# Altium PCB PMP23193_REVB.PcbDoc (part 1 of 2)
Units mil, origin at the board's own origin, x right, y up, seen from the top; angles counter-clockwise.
Board outline 5000 x 3500 mil, 4 copper layers (Component Side, Signal Layer 1, Signal Layer 2, Solder Side), stack 33.234 mil thick; 89 components, 40 nets, 217 pads, 130 vias.
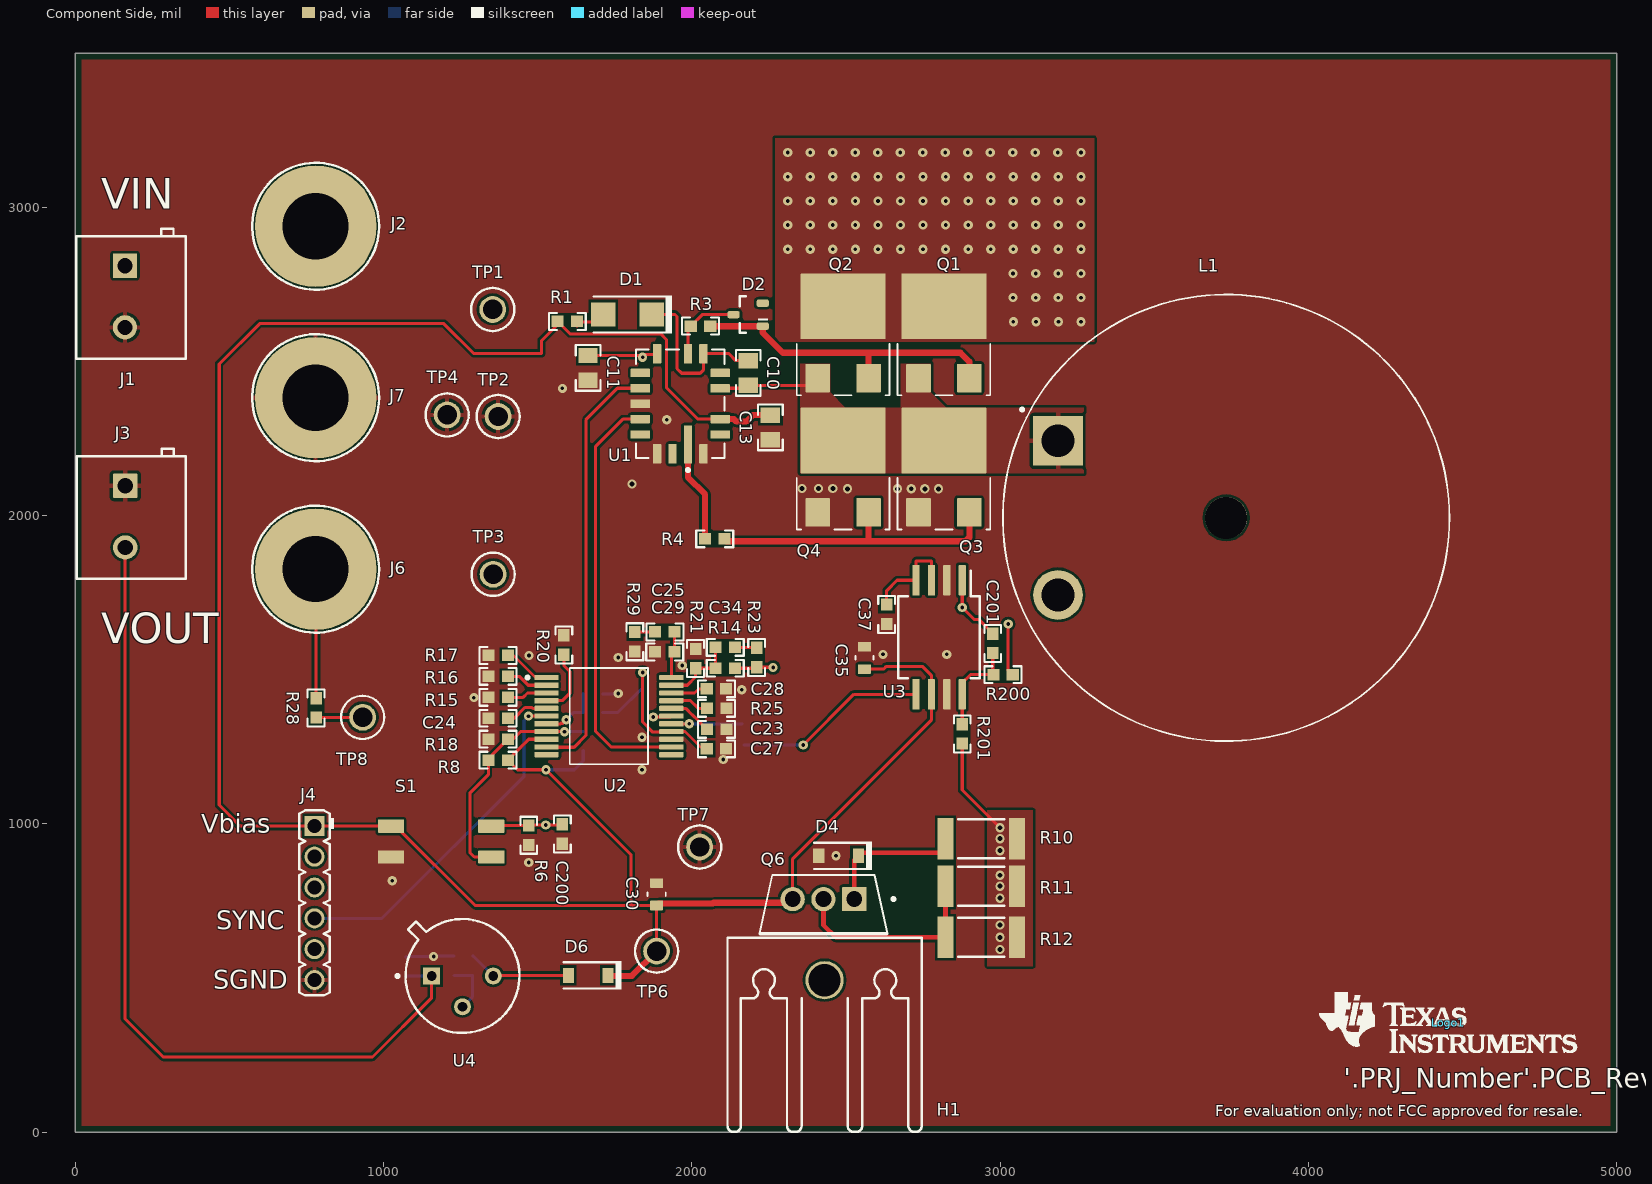
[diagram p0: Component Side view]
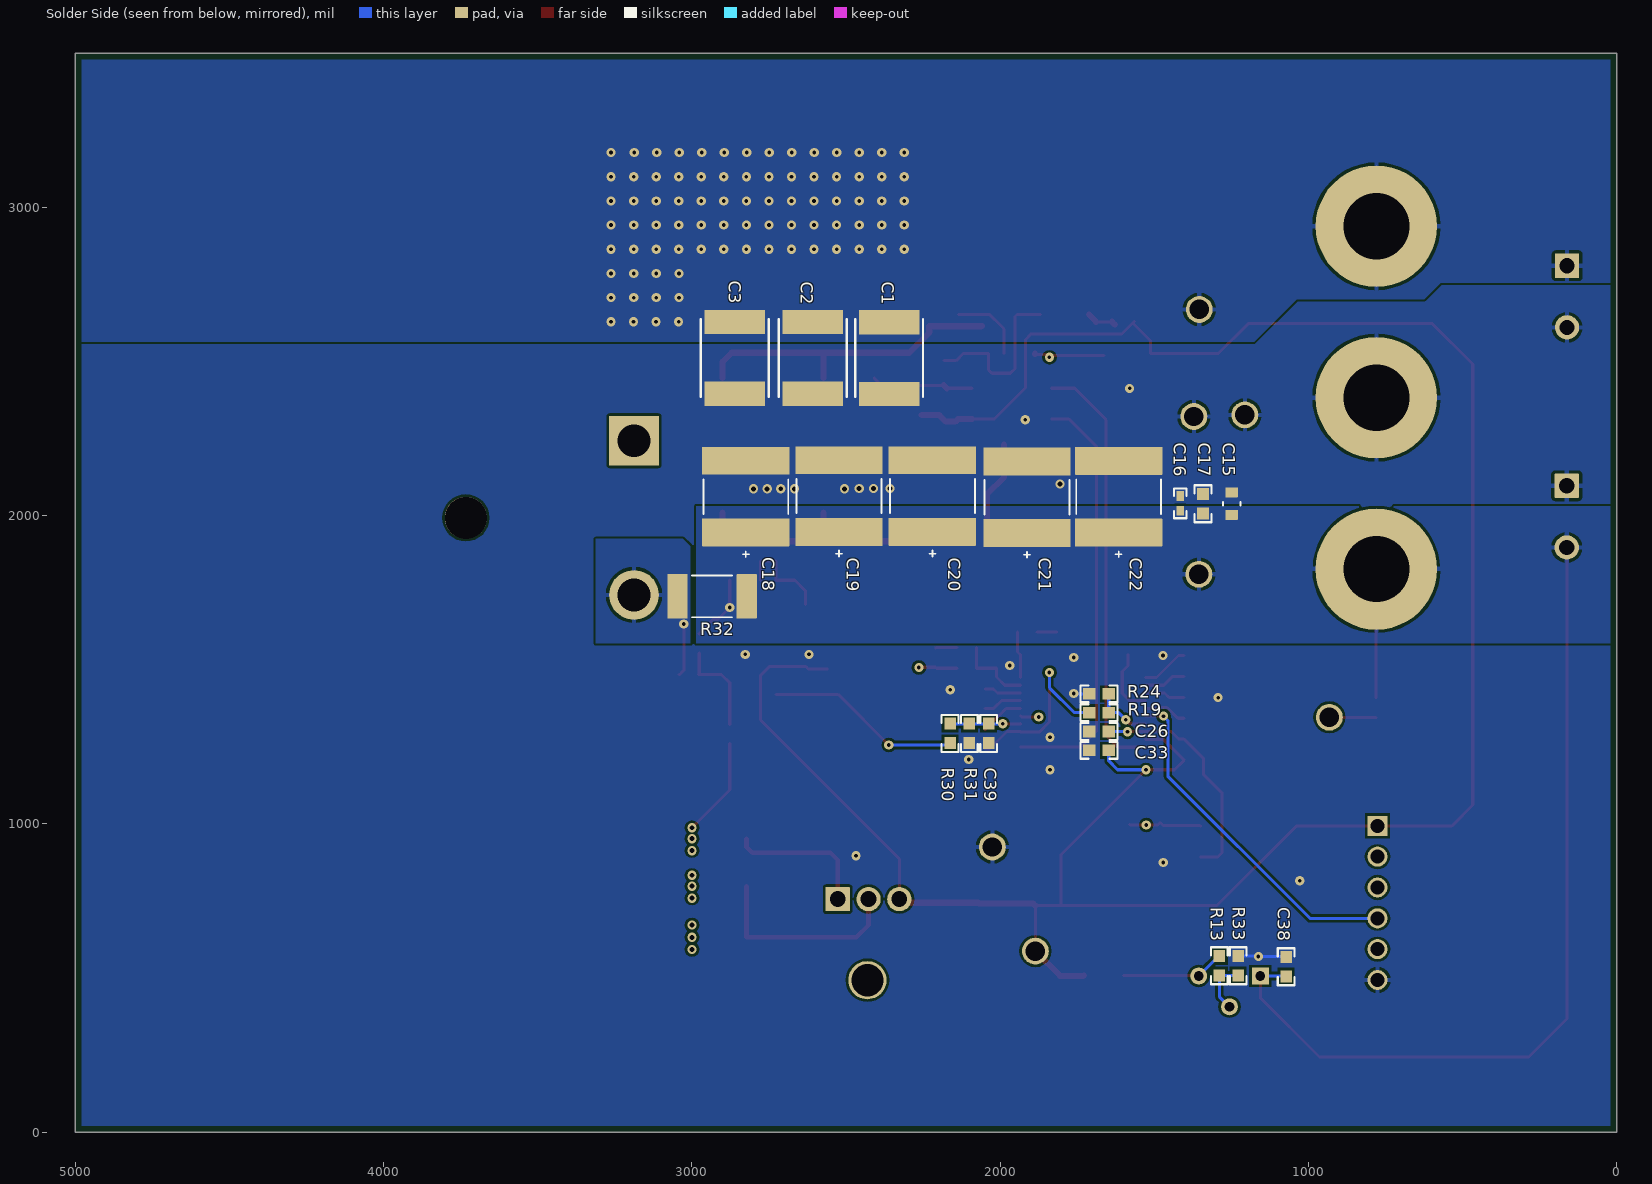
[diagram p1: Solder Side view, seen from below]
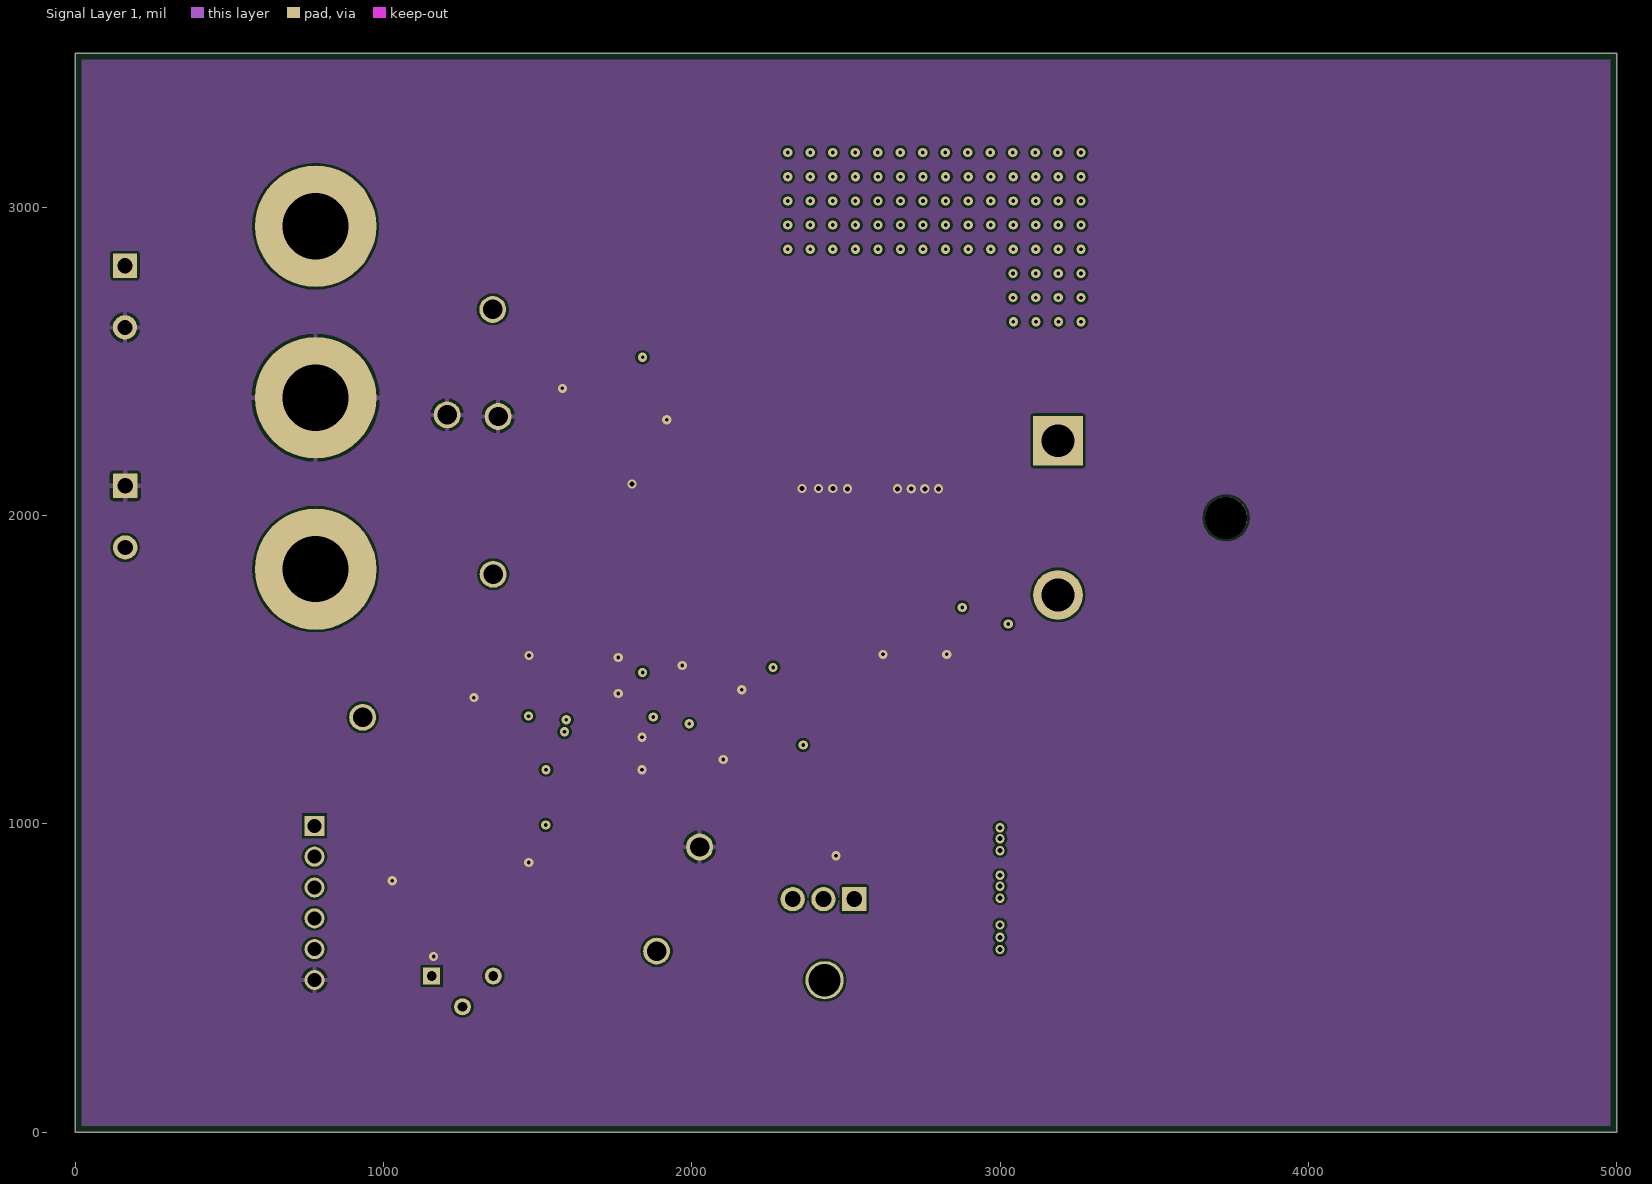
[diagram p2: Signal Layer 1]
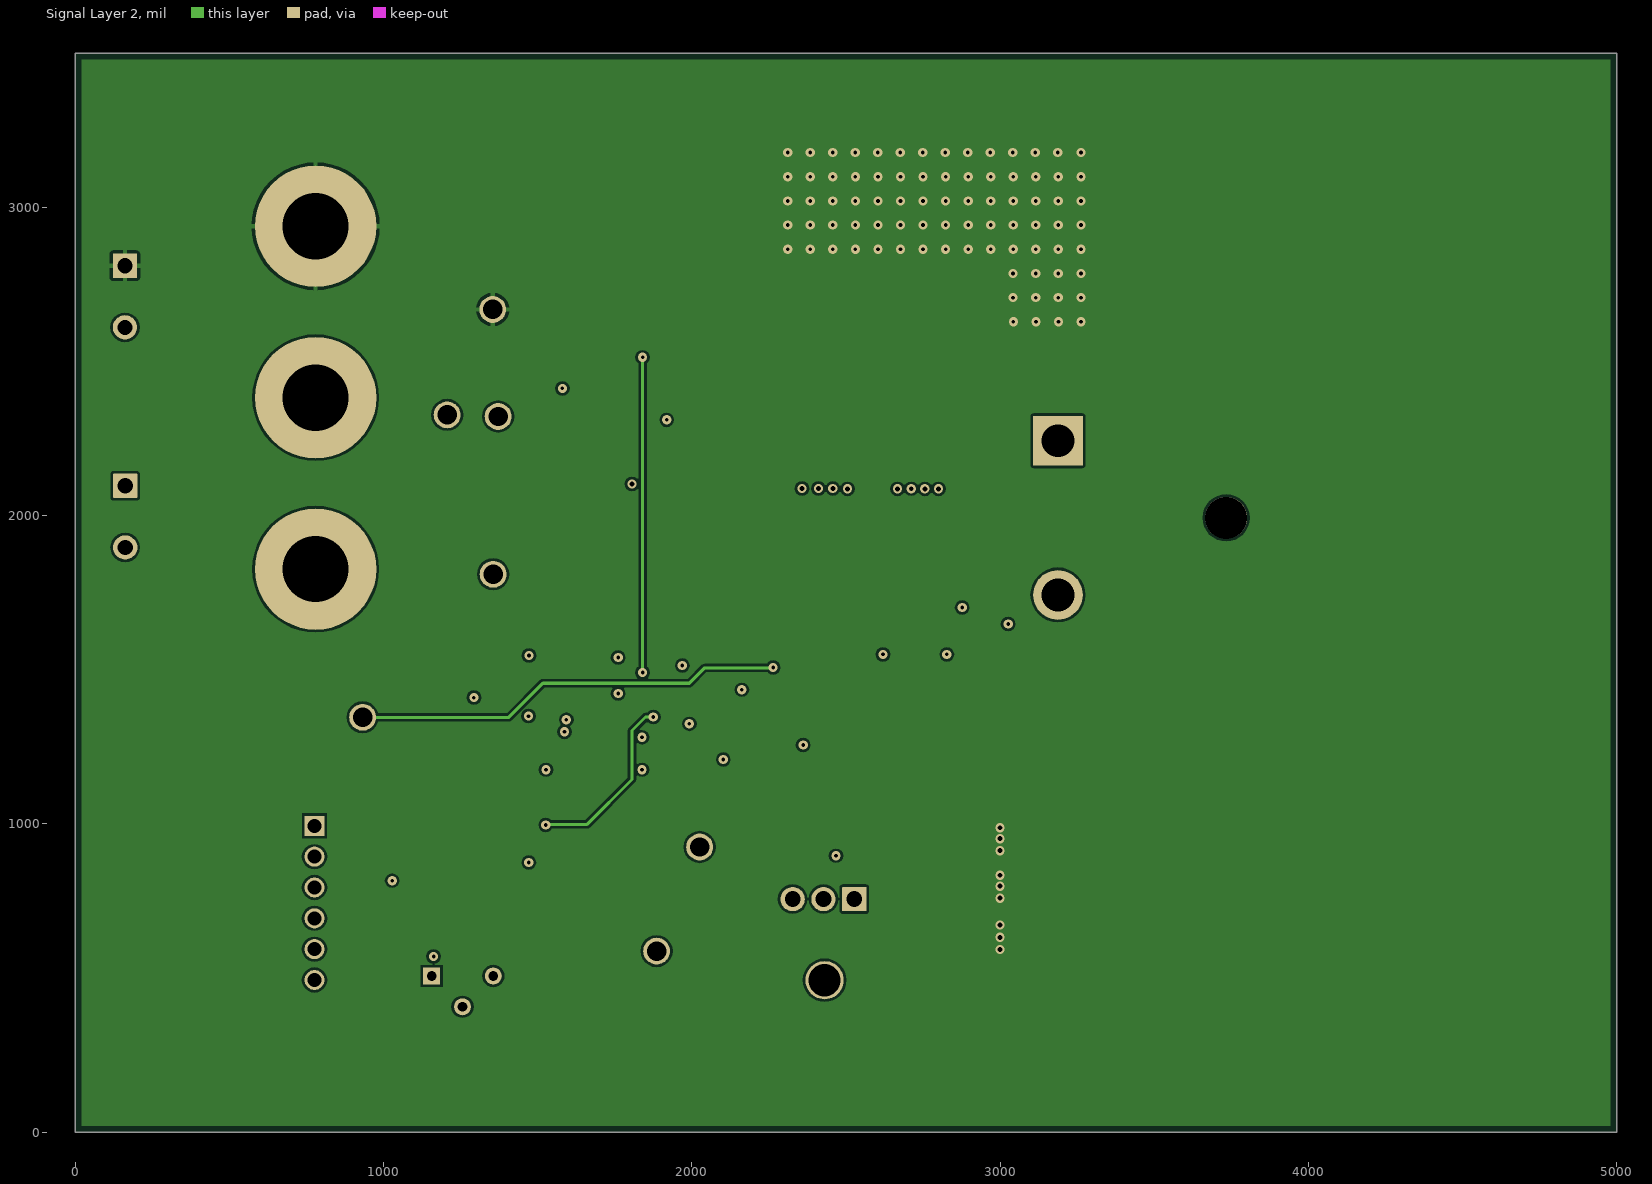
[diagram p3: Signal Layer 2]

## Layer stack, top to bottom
Top Solder: solder mask 0.4, Solder Resist, Dk 3.5
Component Side: signal copper 1.4
Dielectric 1: core 12.6, FR-4, Dk 4.8
Signal Layer 1: signal copper 1.417
Dielectric 3: prepreg 5, Dk 4.2
Signal Layer 2: signal copper 1.417
Dielectric 4: core 10, Dk 4.2
Solder Side: signal copper 1.4
Bottom Solder: solder mask 0.4, Solder Resist, Dk 3.5

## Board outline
0,0 5000,0 5000,3500 0,3500

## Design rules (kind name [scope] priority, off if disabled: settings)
AcuteAngle [All] p1: minimum=5.00000000000000E+0000 checktracksonly=FALSE
AssemblyTestPointUsage [All] p1: valid=2
BoardOutlineClearance BoardOutlineClearance_MountingHoles [OnCopper and InComponentClass('Mounting Holes')] p1: gap=25 ignorepadtopadclearanceinfootprint=FALSE
BoardOutlineClearance BoardOutlineClearance_Poly [OnCopper and InPoly] p2: gap=20 ignorepadtopadclearanceinfootprint=FALSE
BoardOutlineClearance [OnCopper and Not InComponentClass('Logo') and not InComponentClass('FiducialMark') and not InRegion(1000,500,4000,800)] p3: gap=20 ignorepadtopadclearanceinfootprint=FALSE
Clearance Clearance_Keepouts [((IsTrack Or IsArc) And Not InPoly) And IsFree and IsKeepOut vs ((IsTrack Or IsArc) And Not InPoly) And IsFree and IsKeepOut] p1: gap=0 ignorepadtopadclearanceinfootprint=FALSE
Clearance Clearance_Poly [InPolygon] p2: gap=8 ignorepadtopadclearanceinfootprint=FALSE except(0: Arc-Hole Track-Hole SMDPad-Hole THPad-Hole Via-Hole Fill-Hole Poly-Hole Region-Hole Text-Hole)
Clearance [All] p3: gap=7.87 ignorepadtopadclearanceinfootprint=FALSE except(0: Arc-Hole Track-Hole SMDPad-Hole THPad-Hole Via-Hole Fill-Hole Poly-Hole Region-Hole Text-Hole)
ComponentClearance ComponentClearance_MountingHoles_FiducialMarks [InComponentClass('Mounting Holes') vs InComponentClass('FiducialMark')] p1: gap=50 collisioncheckmode=3 verticalgap=10 showdistances=FALSE
ComponentClearance ComponentClearance_Shunt [InComponentClass('Header') vs InComponentClass('Shunt')] p2: gap=0 collisioncheckmode=3 verticalgap=0 showdistances=FALSE
ComponentClearance ComponentClearance_Logo [InComponentClass('Logo')] p3: gap=50 collisioncheckmode=3 verticalgap=10 showdistances=FALSE
ComponentClearance ComponentClearance_ScrewToNut [(HasFootprint('NY PMS 440 0025 PH')) vs (HasFootprint('Keystone_1902C'))] p4: gap=5 collisioncheckmode=3 verticalgap=10 showdistances=FALSE
ComponentClearance ComponentClearance_MountingHoles [InComponentClass('Mounting Holes')] p5: gap=250 collisioncheckmode=3 verticalgap=100000 showdistances=FALSE
ComponentClearance ComponentClearance_SmallPassives [HasFootprint('0201*') or HasFootprint('0402*') or HasFootprint('0508') or HasFootprint('0603*') or HasFootprint('0612') or HasFootprint('0805*') or HasFootprint('0815*') or HasFootprint('0830*') or HasFootprint('1206*') or HasFootprint('1210*') or HasFootprint('1808*') or HasFootprint('1812*') or HasFootprint('1825*') or HasFootprint('2010*') or HasFootprint('2220*') or HasFootprint('2225*') or HasFootprint('2512*') or HasFootprint('2728*') or HasFootprint('3518*') vs HasFootprint('0201*') or HasFootprint('0402*') or HasFootprint('0508') or HasFootprint('0603*') or HasFootprint('0612') or HasFootprint('0805*') or HasFootprint('0815*') or HasFootprint('0830*') or HasFootprint('1206*') or HasFootprint('1210*') or HasFootprint('1808*') or HasFootprint('1812*') or HasFootprint('1825*') or HasFootprint('2010*') or HasFootprint('2220*') or HasFootprint('2225*') or HasFootprint('2512*') or HasFootprint('2728*') or HasFootprint('3518*')] p6: gap=14.96 collisioncheckmode=3 verticalgap=10 showdistances=FALSE
ComponentClearance ComponentClearance_THtoSMT [IsThruComponent vs IsSMTComponent] p7: gap=15 collisioncheckmode=3 verticalgap=30 showdistances=FALSE
ComponentClearance ComponentClearance_THtoTH [IsThruComponent vs IsThruComponent] p8: gap=15 collisioncheckmode=3 verticalgap=30 showdistances=FALSE
ComponentClearance [All] p9: gap=15 collisioncheckmode=3 verticalgap=10 showdistances=FALSE
DiffPairsRouting [All] p1: maxlimit=100 minlimit=10 mostfreqgap=10 toplayer_minwidth=15 toplayer_maxwidth=15 toplayer_prefwidth=15 midlayer1_minwidth=15 midlayer1_maxwidth=15 midlayer1_prefwidth=15 midlayer2_minwidth=15 midlayer2_maxwidth=15 midlayer2_prefwidth=15 bottomlayer_minwidth=15 bottomlayer_maxwidth=15 bottomlayer_prefwidth=15 maxuncoupledlength=1000
FabricationTestPointUsage TestPointUsage [All] p1: valid=2 allowmultiple=FALSE
FabricationTestpoint Testpoint [All] p1: side=3 testpointundercomponent=TRUE minsize=40 maxsize=100 preferedsize=60 minholesize=0 maxholesize=40 preferedholesize=32 testpointgrid=1 allowsidetop=TRUE allowsidebottom=TRUE usegrid=TRUE gridtolerance=0.01
FanoutControl Fanout_LCC [IsLCC] p1: bgadir=Out bgaviamode=Centered fanoutstyle=Auto fanoutdirection=Alternating viagrid=1 // Fanout_LCC (Default Rule)
FanoutControl Fanout_BGA [IsBGA] p2: bgadir=Out bgaviamode=Centered fanoutstyle=Auto fanoutdirection=Alternating viagrid=1 // Fanout_BGA (Default Rule)
FanoutControl Fanout_Default [All] p4: bgadir=Out bgaviamode=Centered fanoutstyle=Auto fanoutdirection=Alternating viagrid=1 // Fanout_Default (Default Rule)
FanoutControl Fanout_Small [(CompPinCount < 5)] p5: bgadir=Out bgaviamode=Centered fanoutstyle=Auto fanoutdirection=OutThenIn viagrid=1 // Fanout_Small (Default Rule)
HoleSize [All] p1: absolutevalues=TRUE maxlimit=251 minlimit=7.87 maxpercent=80.000 minpercent=20.000
MinimumAnnularRing MinimumAnnularRing_ThermalPadVias [IsVia and InAnyComponent] p1: minimumring=5.91
MinimumAnnularRing [All] p2: minimumring=7
MinimumSolderMaskSliver MinimumSolderMaskSliver_Logo [InComponentClass('Logo') vs InComponentClass('Logo')] p1: minsoldermaskwidth=0.7
MinimumSolderMaskSliver [All] p2: minsoldermaskwidth=1
PlaneConnect [All] p1: planeconnectstyle=Direct reliefexpansion=10 reliefentries=4 reliefconductorwidth=10 reliefairgap=10
PolygonConnect [All] p1: thpad.connectstyle=Relief thpad.reliefconductorwidth=15 thpad.reliefentries=4 thpad.polygonreliefangle="90 Angle" thpad.airgapwidth=10 smdpad.connectstyle=Direct smdpad.reliefconductorwidth=10 smdpad.reliefentries=4 smdpad.polygonreliefangle="90 Angle" smdpad.airgapwidth=10 via.connectstyle=Direct via.reliefconductorwidth=10 via.reliefentries=4 via.polygonreliefangle="90 Angle" via.airgapwidth=10
RoutingVias ThermalPadVias [IsVia and InAnyComponent] p1: holewidth=7.87 width=19.68 viastyle="Through Hole" minholewidth=7.87 minwidth=19.68 maxholewidth=12.99 maxwidth=23.62
RoutingVias [All] p2: holewidth=16 width=34 viastyle="Through Hole" minholewidth=7.87 minwidth=26 maxholewidth=40 maxwidth=65
SilkToBoardRegionClearance [Not ((IsComment or IsDesignator) And (Hide <> 'False')) and not InRegion(1000,500,4000,800)] p1:
SilkToSilkClearance SilkToSilkClearance_Pb-FreeLogo [(HasFootprint('Pb-Free_Overlay_Medium') OR HasFootprint('Pb-Free_Overlay_Small')) vs (HasFootprint('Pb-Free_Overlay_Medium') OR HasFootprint('Pb-Free_Overlay_Small'))] p1: silktosilkclearance=0
SilkToSilkClearance [All] p2: silktosilkclearance=1
SilkToSolderMaskClearance SilkToComponentPadClearance [IsPad and InAnycomponent] p1: minsilkscreentomaskgap=0.5 clearancetoexposedcopper=TRUE
SilkToSolderMaskClearance "Silk to Solder Mask Opening" [All] p2: minsilkscreentomaskgap=0.5 clearancetoexposedcopper=FALSE
SolderMaskExpansion [All] p1: expansion=1.97 istentingtop=FALSE
Width [All] p1: maxlimit=100 minlimit=6 preferedwidth=10 checkconnectedcopper=TRUE
15 further rules are at their usual default settings.

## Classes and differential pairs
component class Header: J4
component class Logo: Logo1

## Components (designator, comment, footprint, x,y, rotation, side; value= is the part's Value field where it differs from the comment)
C1 "CKG57NX7T2E335M500JH" CKG57N 2360,2511 r90 bottom value=3.3uF
C2 "CKG57NX7T2E335M500JH" CKG57N 2608,2512 r270 bottom value=3.3uF
C3 "CKG57NX7T2E335M500JH" CKG57N 2861,2512 r270 bottom value=3.3uF
C10 "GRM21BR71H224KA01L" 0805_HV 2182.76,2463.02 r270 top value=0.22uF
C11 "GCJ21BR71H105MA01L" 0805_HV 1663.17,2479.56 r270 top value=1uF
C13 "GCJ21BR71H105MA01L" 0805_HV 2254.61,2286.21 r270 top value=1uF
C15 "CGA4J1X7R1H475K125AC" FP-CGA4J1X7R1H475K125AC_0805-MFG 1249,2039 r270 bottom value=4.7µF
C16 "GCM155R71H104KE02D" 0402 1416,2040 r90 bottom value=0.1uF
C17 "UMK107AB7105KA-T" 0603 1342,2038.8 r90 bottom value=1uF
C18 "T97N476K050HAA" FP-T97N476K050HAA_SMT_CAPACITOR-MFG 2824.92,2062.14 r270 bottom value=47µF
C19 "T97N476K050HAA" FP-T97N476K050HAA_SMT_CAPACITOR-MFG 2522.62,2063.89 r270 bottom value=47µF
C20 "T97N476K050HAA" FP-T97N476K050HAA_SMT_CAPACITOR-MFG 2219.83,2063.89 r270 bottom value=47µF
C21 "T97N476K050HAA" FP-T97N476K050HAA_SMT_CAPACITOR-MFG 1912.8,2060.3 r270 bottom value=47µF
C22 "T97N476K050HAA" FP-T97N476K050HAA_SMT_CAPACITOR-MFG 1615.54,2061.86 r270 bottom value=47µF
C23 "CGA3E3X7R1H474K080AB" 0603 2080.41,1307.12 r0 top value=0.47uF
C24 "CGA3E2X7R1H104K080AA" 0603 1371.55,1343.04 r180 top value=0.1uF
C25 "GRM188R71H563KA93D" 0603 1912.5,1623.04 r180 top value=0.056uF
C26 "UMK107AB7105KA-T" 0603 1679.28,1300.03 r0 bottom value=1uF
C27 "UMK107AB7105KA-T" 0603 2079.77,1243.52 r0 top value=1uF
C28 "CGA3E2X7R1H104K080AA" 0603 2079.77,1438.15 r0 top value=0.1uF
C29 "GRM1885C1H331JA01D" 0603 1912,1558.04 r180 top value=330pF
C30 "C2012X7R1H475K125AC" FP-C2012X7R1H475K125AC_0805-MFG 1885.59,771.83 r270 top
C33 "UMK107AB7105KA-T" 0603 1679.28,1239.01 r0 bottom value=1uF
C34 "GRM1885C2A471JA01D" 0603 2108.22,1573.03 r180 top value=470pF
C35 "C2012X7R1H475K125AC" FP-C2012X7R1H475K125AC_0805-MFG 2560,1538.7 r270 top
C37 "GCM188R71H103KA37D" 0603 2632,1680.04 r270 top value=0.01uF
C38 "CGA3E2X7R1H104K080AA" 0603 1072,537 r90 bottom value=0.1uF
C39 "C0603C102K5RACTU" 0603 2037.21,1294.01 r270 bottom value=1000pF
C200 "C1608C0G1H101J080AE" 0603 1579.88,967.5 r270 top value=100pF
C201 "GCM188R71H103KA37D" 0603 2976.09,1585.69 r90 top value=0.01uF
D1 "US1D-E3/61T" SMA 1791.02,2652.71 r180 top value=200V
D2 "BAS16-7-F" SOT-23 2182.76,2652.15 r180 top value=75V
D4 "MMSZ4700-E3-08" SOD-123 2476.1,896.83 r180 top value=13V
D6 "BAT54T1G" SOD-123 1664,509 r180 top value=30V
H1 "V7700W" ASMN_V7700W 2430.69,493.29 r180 top
J1 "ED120/2DS" On-Shore_ED120_2DS 161.1,2710.97 r270 top
J2 "575-8" Keystone575-8 779.7,2938.92 r180 top
J3 "ED120/2DS" On-Shore_ED120_2DS 162,1997 r270 top
J4 "61300611121" WURTH_61300611121 776,744 r270 top
J6 "575-8" Keystone575-8 779.7,1826.72 r180 top
J7 "575-8" Keystone575-8 779.7,2382.82 r0 top
L1 "S69833" FP-S69833_PTH2_D1IN43-MFG 3733,1993.04 r90 top value=12.67uH
Logo1 "Texas Instruments" TI_Stacked_Overlay_Small 4453,356 r0 top
Logo2 "FCC disclaimer" FCC_disclaimer 9603.25,8023.07 r90 top
Q1 "IRHNJ9A7234" FP-IRHNJ9A7234_SMD3-MFG 2817.6,2593.03 r0 top locked
Q2 "IRHNJ9A7234" FP-IRHNJ9A7234_SMD3-MFG 2490.83,2593.03 r0 top locked
Q3 "IRHNJ9A7234" FP-IRHNJ9A7234_SMD3-MFG 2817.6,2157.63 r0 top locked
Q4 "IRHNJ9A7234" FP-IRHNJ9A7234_SMD3-MFG 2490.83,2157.63 r0 top locked
Q6 "BUX85G" FP-BUX85G_TO-220-3-MFG 2426.93,739.33 r270 top value=450V
R1 "CRCW06031R10FKEA" 0603 1596.06,2630.04 r0 top value=1.10
R3 "CRCW06035R10JNEA" 0603 2027.96,2615.29 r0 top value=5.1
R4 "RMCF0603ZT0R00" 0603 2074.22,1924.67 r0 top value=0
R6 "RC0603FR-07100KL" 0603 1471,963.5 r90 top value=100k
R8 "CRCW060314K7FKEA" 0603 1371.55,1207.16 r0 top value=14.7k
R10 "CRCW251251K0JNEG" 2512 2938.74,952.36 r0 top value=51k
R11 "CRCW25122K00FKEG" 2512 2938.74,798.41 r0 top value=2.00k
R12 "CRCW25122K00FKEG" 2512 2938.74,632.46 r0 top value=2.00k
R13 "RC0603FR-07240RL" 0603 1288.96,540 r90 bottom value=240
R14 "CRCW060375K0FKEA" 0603 2108.22,1505.22 r0 top value=75.0k
R15 "CRCW060375K0FKEA" 0603 1371.55,1410.88 r0 top value=75.0k
R16 "CRCW060375K0FKEA" 0603 1371.55,1478.78 r0 top value=75.0k
R17 "CRCW06031M10FKEA" 0603 1371.55,1546.69 r0 top value=1.10Meg
R18 "CRCW06031K00FKEA" 0603 1371.55,1275.07 r0 top value=1.00k
R19 "RCS06030000Z0EA" 0603 1679.28,1361.05 r0 bottom value=0
R20 "RC0603FR-07100KL" 0603 1584.63,1580.69 r270 top value=100k
R21 "CRCW06031K65FKEA" 0603 2011.93,1536.71 r270 top value=1.65k
R23 "CRCW06037K50FKEA" 0603 2209.99,1540 r270 top value=7.50k
R24 "RCS06030000Z0EA" 0603 1679.28,1422 r180 bottom value=0
R25 "CRCW0603332KFKEA" 0603 2080.41,1375.02 r180 top value=332k
R28 "RC0603FR-0720RL" 0603 781,1376.54 r90 top value=20.0
R29 "CRCW060320K0FKEA" 0603 1815,1591.04 r90 top value=20.0k
R30 "CRCW06031K00FKEA" 0603 2162.59,1294.01 r270 bottom value=1.00k
R31 "CRCW0603249RFKEA" 0603 2100,1294.01 r90 bottom value=249
R32 "WSLP2512R0100FEA" FP-WSLP2512R0100FEA_2512-MFG 2934.38,1738.27 r180 bottom value=10m
R33 "RC0603FR-072K4L" 0603 1228,540 r270 bottom value=2.40k
R200 "CRCW06031K00FKEA" 0603 3009.39,1484.66 r180 top value=1.00k
R201 "CRCW06031M10FKEA" 0603 2877,1292.05 r270 top value=1.10Meg
S1 "A6SN-2104" SW_A6SN-2104 1187,943.04 r180 top
TP1 "5010" Keystone5010 1354,2669.04 r0 top
TP2 "5011" Keystone5011 1371.55,2321.85 r0 top
TP3 "5010" Keystone5010 1355.35,1810 r0 top
TP4 "5011" Keystone5011 1206.14,2326.93 r0 top
TP6 "5010" Keystone5010 1885.59,587.78 r0 top
TP7 "5011" Keystone5011 2025.2,925.38 r0 top
TP8 "5128" Keystone5128 932,1346 r0 top
U1 "RIC7S113E4SCS" FP-RIC7S113E4SCS_LCC18_CIC-IPC_C 1962.28,2363.34 r90 top
U2 "TPS7H5001HFT/EM" HFT0022A-C01-MFG 1731,1350.02 r0 top
U3 "INA901HKX/EM" HKX0008A_Custom_A 2802,1605.69 r270 top
U4 "LM117H" NDT0003A 1256,507.04 r0 top

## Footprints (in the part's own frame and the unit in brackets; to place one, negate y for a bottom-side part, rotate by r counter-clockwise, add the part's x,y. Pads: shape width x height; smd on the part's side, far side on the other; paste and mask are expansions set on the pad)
0402 [mm] "0402 from SM-752 data"
  rect 0.8x0.6 smd: 1(-0.6,0) 2(0.6,0)
  silkscreen extent -1.22,-0.52 1.22,0.52, body extent -0.55,-0.3 0.55,0.3, height 0.6
0603 [mm] "0603 from SM-752 data"
  rect 1x0.95 smd: 1(-0.8,0) 2(0.8,0)
  silkscreen extent -1.52,-0.69 1.52,0.69, body extent -0.87,-0.47 0.87,0.47, height 1
0805_HV [mil] "0805 with 30mil clearance between pads"
  rect 50x63 smd: 1(-40,0) 2(40,0)
  silkscreen extent -74,-40 74,40, body extent -43,-29 43,29, height 57
2512 [mm] "Chip Resistor, Body 6.3x3.2mm, IPC Medium Density"
  rect 1.3x3.4 smd: 1(-2.95,0) 2(2.95,0)
  silkscreen extent -1.9,-1.6 1.9,1.6, body extent -3.22,-1.67 3.22,1.67, height 0.71
ASMN_V7700W [mm] "Heat Sink SOT-32, TO-220"
  round 3.15 hole 2.65: 1(0,0)
  silkscreen extent -8,-3.5 8,12.5, body extent -8,-3.5 8,12.5, height 25
CKG57N [mm] "Chip Capacitor, Body 6.0x5.0x5.0mm,"
  rect 2x5 smd: 1(-2.95,0) 2(2.95,0)
  silkscreen extent -3.2,-2.8 3.2,2.8, body extent -3.3,-2.75 3.3,2.75, height 5.5
FCC_disclaimer [mil]
FP-BUX85G_TO-220-3-MFG [mm]
  rrect5% 2x2 hole 1.3 paste-1000 mask+0: 1(-0.433,2.54)
  round 2 hole 1.3 paste-1000 mask+0: 2(-0.433,0) 3(-0.433,-2.54)
  silkscreen extent -2.41,-5.27 2.41,5.89, body extent -2.51,-5.37 2.51,5.37, height 0.25
FP-C2012X7R1H475K125AC_0805-MFG [mm]
  rrect13% 0.8x1.05 smd paste+0 mask+0: 1(-0.925,0) 2(0.925,0)
  silkscreen extent -0.15,-0.75 0.15,0.75, body extent -1.43,-0.85 1.43,0.85, height 0.25
FP-CGA4J1X7R1H475K125AC_0805-MFG [mm]
  rrect13% 0.8x1.05 smd paste+0 mask+0: 1(-0.925,0) 2(0.925,0)
  silkscreen extent -0.15,-0.72 0.15,0.72, body extent -1,-0.63 1,0.63, height 1.45
FP-IRHNJ9A7234_SMD3-MFG [mil]
  rrect2% 276x213 smd paste+0 mask+0: 1(0,86.25)
  rrect5% 80x92 smd paste+0 mask+0: 2(82.5,-146.75) 3(-82.5,-146.75)
  silkscreen extent -150,-202 150,-35, body extent -148,-200 148,200, height 123
FP-RIC7S113E4SCS_LCC18_CIC-IPC_C [mm]
  rrect15% 3.141x0.684 smd paste+0 mask+0: 1(-3.357,-0.635)
  rrect15% 1.616x0.684 smd paste+0 mask+0: 2(-4.12,-1.905) 8(4.12,-1.905) 9(4.12,-0.635) 11(4.12,1.905) 17(-4.12,1.905) 18(-4.12,0.635)
  rrect15% 0.684x1.616 smd paste+0 mask+0: 3(-2.54,-3.295) 4(-1.27,-3.295) 6(1.27,-3.295) 7(2.54,-3.295) 12(2.54,3.295) 13(1.27,3.295) 14(0,3.295) 15(-1.27,3.295) 16(-2.54,3.295)
  silkscreen extent -5.59,-3.65 4.48,3.65, body extent -4.48,-3.65 4.48,3.65, height 3.22
FP-S69833_PTH2_D1IN43-MFG [mm]
  rrect2% 4.1x4.1 hole 2.7 paste-1000 mask+0: 1(6.35,13.854)
  round 4.1 hole 2.7 paste-1000 mask+0: 2(-6.35,13.854)
  round 3.454 hole 3.454 unplated paste-1000 mask+0: ""(0,0)
  silkscreen extent -18.4,-18.4 18.4,18.4, body extent -18.16,-18.16 18.16,18.17, height 19.05
FP-T97N476K050HAA_SMT_CAPACITOR-MFG [mm]
  rrect4% 2.3x7.2 smd paste+0 mask+0: 1(-2.95,0) 2(2.95,0)
  silkscreen extent -1.43,-3.5 5,3.5, body extent -3.2,-3.3 4.8,3.3, height 6.8
FP-WSLP2512R0100FEA_2512-MFG [mm]
  rrect6% 1.65x3.68 smd paste+0 mask+0: 1(-2.855,0) 2(2.855,0)
  silkscreen extent -1.65,-1.72 1.66,1.72, body extent -3.18,-1.59 3.18,1.59, height 0.89
HFT0022A-C01-MFG [mm]
  rrect23% 2x0.435 smd paste+0 mask+0: 1(-5.145,3.175) 2(-5.145,2.54) 3(-5.145,1.905) 4(-5.145,1.27) 5(-5.145,0.635) 6(-5.145,0) 7(-5.145,-0.635) 8(-5.145,-1.27) 9(-5.145,-1.905) 10(-5.145,-2.54) 11(-5.145,-3.175) 12(5.145,-3.175) 13(5.145,-2.54) 14(5.145,-1.905) 15(5.145,-1.27) 16(5.145,-0.635) 17(5.145,0) 18(5.145,0.635) 19(5.145,1.27) 20(5.145,1.905) 21(5.145,2.54) 22(5.145,3.175)
  silkscreen extent -6.83,-3.97 3.23,3.97, body extent -5.78,-3.85 5.78,3.85, height 2.43
HKX0008A_Custom_A [mm] "CFP, 8-Leads, Body 6.475x6.485mm, Pitch 1.27mm"
  rrect17% 2.5x0.6 smd: 1(-4.7,1.905) 2(-4.7,0.635) 3(-4.7,-0.635) 4(-4.7,-1.905) 5(4.7,-1.905) 6(4.7,-0.635) 7(4.7,0.635) 8(4.7,1.905)
  silkscreen extent -5.5,-3.36 3.37,3.36, body extent -3.25,-3.24 3.25,3.24, height 2.51
Keystone575-8 [mm] "Banana Jack"
  round 10 hole 5.45: 1(0,0)
  silkscreen extent -5.23,-5.23 5.23,5.23, body extent -3.92,-3.94 3.95,3.94, height 2.36
Keystone5010 [mil] "Keystone Multipurpose loops"
  round 87 hole 63: 1(0,0)
  silkscreen extent -70,-70 70,70, body extent -63,-63 63,62, height 319
Keystone5011 [mil] "Keystone Multipurpose loops"
  round 87 hole 63: 1(0,0)
  silkscreen extent -70,-70 70,70, body extent -63,-63 63,62, height 319
Keystone5128 [mil] "Keystone Multipurpose loops"
  round 87 hole 63: 1(0,0)
  silkscreen extent -70,-70 70,70, body extent -63,-63 63,62, height 319
NDT0003A [mm] "Can; 3 Leads; Pin Circle Dia. 5.08 mm; Lead Dia. 0.48 mm (max)"
  rect 1.4x1.4 hole 0.8: 1(-2.54,0)
  round 1.4 hole 0.8: 2(0,-2.54) 3(2.54,0)
  silkscreen extent -5.47,-4.69 4.69,4.69, body extent -4.69,-4.69 4.69,4.69, height 4.7
On-Shore_ED120_2DS [mm] "ONSHORE"
  rrect5% 2x2 hole 1.25: 1(-2.54,0)
  round 2 hole 1.25: 2(2.54,0)
  silkscreen extent -5.6,-4 5.12,5, body extent -5.78,-4 5.08,5, height 13
SMA [mm] "Molded Diode, 2-Leads, Body 4.3x2.6mm, IPC Medium Density, based on OnSemi component dimensions and land pattern"
  rect 2x2 smd: 1(-2,0) 2(2,0)
  silkscreen extent -3.66,-1.57 2.79,1.57, body extent -2.6,-1.3 2.6,1.3, height 2.42
SOD-123 [mm] "On Semi recommended land pattern"
  rect 0.915x1.22 smd: 1(-1.637,0) 2(1.637,0)
  silkscreen extent -2.74,-1.17 2.03,1.17, body extent -1.93,-0.9 1.93,0.9, height 1.35
SOT-23 [mm] "SOT23, 3-Leads, Body 2.9x1.3mm, Pitch 0.95mm, Lead Span 2.5mm, IPC Medium Density"
  rrect50% 1x0.6 smd: 1(-1.2,0.95) 2(-1.2,-0.95) 3(1.2,0)
  silkscreen extent -1.62,-1.5 0.7,1.5, body extent -1.16,-1.45 1.21,1.45, height 1
SW_A6SN-2104 [mm] "SMD, 4-Leads, Body 7x7.5mm, Pitch 2.54mm"
  rrect9% 2.15x1.1 smd: 1(-4.125,1.27) 2(-4.125,-1.27) 3(4.125,-1.27) 4(4.125,1.27)
  body extent -4.65,-3.5 4.65,3.5, height 5.55
TI_Stacked_Overlay_Small [mil]
  silkscreen extent -418,-98 418,98
WURTH_61300611121 [mm] "Header, 2.54mm, 6x1, TH"
  rect 1.65x1.65 hole 1.15: 1(-6.35,0)
  round 1.65 hole 1.15: 2(-3.81,0) 3(-1.27,0) 4(1.27,0) 5(3.81,0) 6(6.35,0)
  silkscreen extent -7.62,-1.27 7.62,1.6, body extent -7.62,-1.27 7.62,1.27, height 8.54

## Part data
C1 C2 C3: library part CMP-0009427-1, "CAP, CERM, 3.3 uF, 250 V, +/- 20%, X7T, AEC-Q200 Grade 1, 6x5x5mm", Cap_Case=2220, Manufacturer=TDK, Supplier Part Number 1=445-7108-1-ND, TempCo=X7T, Tolerance_%=20%, Value1=Unknown, Value2=250V, ValueDisplayed=3.3uF
C10: library part CMP-0008354-2, "CAP, CERM, 0.22 uF, 50 V, +/- 10%, X7R, 0805", Cap_Case=0805, Manufacturer=MuRata, Supplier Part Number 1=490-1670-1-ND, TempCo=X7R, Tolerance_%=10%, Value1=Unknown, Value2=50V, ValueDisplayed=0.22uF
C11 C13: library part CMP-0080480-1, "CAP, CERM, 1 µF, 50 V,+/- 20%, X7R, AEC-Q200 Grade 1, 0805", Cap_Case=0805, Manufacturer=MuRata, Supplier Part Number 1=490-16470-1-ND, TempCo=X7R, Tolerance_%=20%, Value2=50V, ValueDisplayed=1µF
C15: library part CMP-0090082-1, "Cap Ceramic 4.7uF 50V X7R 10% Pad SMD 0805 +125°C Automotive T/R", Manufacturer="TDK Corporation", Operating Temperature Range="-55°C to +125°C", TempCo=15%, Temperature Characteristic=X7R, Tolerance_%=0.1%, ValueDisplayed=4.7uF
C16: library part CMP-0006356-2, "CAP, CERM, 0.1 uF, 50 V, +/- 10%, X7R, AEC-Q200 Grade 1, 0402", Cap_Case=0402, Manufacturer=MuRata, Supplier Part Number 1=490-10672-1-ND, TempCo=X7R, Tolerance_%=10%, Value1=Unknown, Value2=50V, ValueDisplayed=0.1uF
C17 C26 C27 C33: library part CMP-0007508-5, "CAP, CERM, 1 uF, 50 V, +/- 10%, X7R, 0603", Cap_Case=0603, Manufacturer="Taiyo Yuden", Supplier Part Number 1=587-3247-1-ND, TempCo=X7R, Tolerance_%=10%, Value1=Unknown, Value2=50V, ValueDisplayed=1uF
C18 C19 C20 C21 C22: library part CMP-0094686-1, "Solid Tantalum Chip Capacitors TANTAMOUNT™, Hi-Rel COTS, Ultra-Low ESR, Conformal Coated Case", Leakage Current=23.5uA, Manufacturer=Vishay, Operating Temperature Range="-55°C to +125°C", Tolerance_%=10%, ValueDisplayed=47uF
C23: library part CMP-0007096-4, "CAP, CERM, 0.47 uF, 50 V, +/- 10%, X7R, AEC-Q200 Grade 1, 0603", Cap_Case=0603, Manufacturer=TDK, Supplier Part Number 1=810-CGA3E3X7R1H474K080AB, TempCo=X7R, Tolerance_%=10%, Value1="0.01064 ohm", Value2=50V, ValueDisplayed=0.47uF
C24 C28 C38: library part CMP-0007078-4, "CAP, CERM, 0.1 uF, 50 V, +/- 10%, X7R, AEC-Q200 Grade 1, 0603", Cap_Case=0603, Manufacturer=TDK, Supplier Part Number 1=445-5666-1-ND, TempCo=X7R, Tolerance_%=10%, Value1="0.0296 ohm", Value2=50V, ValueDisplayed=0.1uF
C25: library part CMP-0007460-1, "CAP, CERM, 0.056 uF, 50 V, +/- 10%, X7R, 0603", Cap_Case=0603, Manufacturer=MuRata, Supplier Part Number 1=81-GRM188R71H563KA93, TempCo=X7R, Tolerance_%=10%, Value1=Unknown, Value2=50V, ValueDisplayed=0.056uF
C29: library part CMP-0007209-4, "CAP, CERM, 330 pF, 50 V, +/- 5%, C0G/NP0, 0603", Cap_Case=0603, Manufacturer=MuRata, Supplier Part Number 1=490-1439-1-ND, TempCo=C0G/NP0, Tolerance_%=5%, Value1=Unknown, Value2=50V, ValueDisplayed=330pF
C30 C35: library part CMP-0088943-1, "4.7µF ±10% 50V Ceramic Capacitor X7R 0805 (2012 Metric)", Digikey Part Number=445-C2012X7R1H475K125ACCT-ND, Manufacturer=TDK, Mouser Part Number=810-C2012X7R475K125C, Operating Temperature Range="-55°C to +125°C", TempCo=15%, Temperature Characteristic=X7R, Tolerance_%=10%, ValueDisplayed=4.7uF
C34: library part CMP-0007272-3, "CAP, CERM, 470 pF, 100 V, +/- 5%, C0G/NP0, 0603", Cap_Case=0603, Manufacturer=MuRata, Supplier Part Number 1=490-1367-1-ND, TempCo=C0G/NP0, Tolerance_%=5%, Value1=Unknown, Value2=100V, ValueDisplayed=470pF
C37 C201: library part CMP-0007143-4, "CAP, CERM, 0.01 uF, 50 V, +/- 10%, X7R, AEC-Q200 Grade 1, 0603", Cap_Case=0603, Manufacturer=MuRata, Supplier Part Number 1=490-4778-1-ND, TempCo=X7R, Tolerance_%=10%, Value1=Unknown, Value2=50V, ValueDisplayed=0.01uF
C39: library part CMP-0006847-4, "CAP, CERM, 1000 pF, 50 V, +/- 10%, X7R, 0603", Cap_Case=0603, Manufacturer=Kemet, Supplier Part Number 1=399-1082-1-ND, TempCo=X7R, Tolerance_%=10%, Value1=Unknown, Value2=50V, ValueDisplayed=1000pF
C200: library part CMP-0006989-4, "CAP, CERM, 100 pF, 50 V, +/- 5%, C0G/NP0, 0603", Cap_Case=0603, Manufacturer=TDK, Supplier Part Number 1=445-173611-1-ND, TempCo=C0G/NP0, Tolerance_%=5%, Value1=Unknown, Value2=50V, ValueDisplayed=100pF
D1: library part CMP-0029189-2, "Diode, Ultrafast, 200 V, 1 A, AEC-Q101, SMA", Manufacturer=Vishay-Semiconductor, Value1=1A, Value2=1V
D2: library part CMP-0029005-1, "Diode, Ultrafast, 75 V, 0.3 A, SOT-23", Manufacturer="Diodes Inc.", Supplier Part Number 1=BAS16FSCT-ND, Value1=0.3A, Value2=1.125V
D4: library part CMP-0077610-3, "Diode, Zener, 13 V, 500 mW, SOD-123", Manufacturer=Vishay-Semiconductor, Power_W=500mW, Value1=0.5W
D6: library part CMP-0028457-1, "Diode, Schottky, 30 V, 0.2 A, SOD-123", Manufacturer="ON Semiconductor", Supplier Part Number 1=88H4554, Value1=0.2A, Value2=0.8V
H1: library part CMP-0067644-1, "Heatsink SOT-32, TO-220", Manufacturer="Assman WSW", Supplier Part Number 1=AE10850-ND
J1 J3: library part CMP-0074910-1, "Terminal Block, 5.08 mm, 2x1, Brass, TH", Color=Blue, Current_A=15A, Manufacturer="On-Shore Technology", Supplier Part Number 1=ED1609-ND, Voltage_V=300V
J2 J6 J7: library part CMP-0055166-1, "Standard Banana Jack, Uninsulated, 8.9mm", Manufacturer=Keystone, Supplier Part Number 1=36-575-8-ND
J4: library part CMP-0054801-1, "Header, 2.54 mm, 6x1, Gold, TH", Manufacturer="Wurth Elektronik", Supplier Part Number 1=732-5319-ND
L1: library part CMP-0094619-1, "500kHz DC Inductor for PMP23139", Manufacturer="Renco Electronics", Operating Temperature Range=to, Test Frequency=500kHz, Tolerance_%=10%
Logo1: library part CMP-0074838-1, "Texas Instrument Corporate Signature"
Logo2: library part CMP-0074847-1, "FCC_disclaimer"
Q1 Q2 Q3 Q4: library part CMP-0094197-1, "Rad hard, 250V, 17A, single, N-channel MOSFET, R9 in a SMD-0.5 package", Drain To Source Breakdown Voltage=250V, Input Capacitace At Vds="1510pF @ 25V", Manufacturer=Infineon, Operating Temperature Range="-55°C to +150°C", Power_W=75W, Pulse Drain Current=68A
Q6: library part CMP-0094657-1, "Bipolar (BJT) Transistor NPN 450 V 2 A 4MHz 50 W Through Hole TO-220", Digikey Part Number=BUX85GOS-ND, Emitter Base Voltage=5V, Manufacturer="On Semiconductor", Mouser Part Number=863-BUX85G, Operating Temperature Range="-65°C to +150°C", Power_W=50W
R1: library part CMP-0022174-4, "RES, 1.10, 1%, 0.1 W, AEC-Q200 Grade 0, 0603", Manufacturer=Vishay-Dale, Power_W=100mW, Supplier Part Number 1=541-1.10HHCT-ND, TempCo="100 ppm/C", Tolerance_%=1%, Value2=0.1W, Value_Code=1R10, ValueDisplayed=1.10
R3: library part CMP-0025834-4, "RES, 5.1, 5%, 0.1 W, AEC-Q200 Grade 0, 0603", Manufacturer=Vishay-Dale, Power_W=100mW, Supplier Part Number 1=541-5.1GCT-ND, TempCo="200 ppm/C", Tolerance_%=5%, Value2=0.1W, Value_Code=5R10, ValueDisplayed=5.1
R4: library part CMP-0023343-3, "RES, 0, 1%, 0.1 W, AEC-Q200 Grade 0, 0603", Manufacturer="Stackpole Electronics Inc", Power_W=100mW, Supplier Part Number 1=RMCF0603ZT0R00CT-ND, TempCo=ppm/C, Tolerance_%=1%, Value2=0.1W, Value_Code=0
R6 R20: library part CMP-0022735-5, "RES, 100 k, 1%, 0.1 W, 0603", Manufacturer=Yageo, Power_W=100mW, Supplier Part Number 1=311-100KHRCT-ND, TempCo="100 ppm/C", Tolerance_%=1%, Value2=0.1W, Value_Code=100k
R8: library part CMP-0022056-4, "RES, 14.7 k, 1%, 0.1 W, AEC-Q200 Grade 0, 0603", Manufacturer=Vishay-Dale, Power_W=100mW, Supplier Part Number 1=541-14.7KHCT-ND, TempCo="100 ppm/C", Tolerance_%=1%, Value2=0.1W, Value_Code=14k7, ValueDisplayed=14.7k
R10: library part CMP-0015977-1, "RES, 51 k, 5%, 1 W, AEC-Q200 Grade 0, 2512", Manufacturer=Vishay-Dale, Power_W=1W, Supplier Part Number 1=541-51KXCT-ND, TempCo="200 ppm/C", Tolerance_%=5%, Value_Code=51k0, ValueDisplayed=51k
R11 R12: library part CMP-0015569-3, "RES, 2.00 k, 1%, 1 W, AEC-Q200 Grade 0, 2512", Manufacturer=Vishay-Dale, Power_W=1W, Supplier Part Number 1=541-2.00KAFCT-ND, TempCo="100 ppm/C", Tolerance_%=1%, Value_Code=2k00, ValueDisplayed=2.00k
R13: library part CMP-0022938-5, "RES, 240, 1%, 0.1 W, 0603", Manufacturer=Yageo, Power_W=100mW, Supplier Part Number 1=311-240HRCT-ND, TempCo="100 ppm/C", Tolerance_%=1%, Value2=0.1W, Value_Code=240R, ValueDisplayed=240
R14 R15 R16: library part CMP-0022589-4, "RES, 75.0 k, 1%, 0.1 W, AEC-Q200 Grade 0, 0603", Manufacturer=Vishay-Dale, Power_W=100mW, Supplier Part Number 1=541-75.0KHCT-ND, TempCo="100 ppm/C", Tolerance_%=1%, Value2=0.1W, Value_Code=75k0, ValueDisplayed=75.0k
R17 R201: library part CMP-0022142-4, "RES, 1.10 M, 1%, 0.1 W, AEC-Q200 Grade 0, 0603", Manufacturer=Vishay-Dale, Power_W=100mW, Supplier Part Number 1=541-1.10MHCT-ND, TempCo="100 ppm/C", Tolerance_%=1%, Value2=0.1W, Value_Code=1M10, ValueDisplayed=1.10M
R18 R30 R200: library part CMP-0022109-5, "RES, 1.00 k, 1%, 0.1 W, AEC-Q200 Grade 0, 0603", Manufacturer=Vishay-Dale, Power_W=100mW, Supplier Part Number 1=541-1.00KHCT-ND, TempCo="100 ppm/C", Tolerance_%=1%, Value2=0.1W, Value_Code=1k00, ValueDisplayed=1.00k
R19 R24: library part CMP-0081973-1, "RES, 0, 0%, 0.25 W, AEC-Q200 Grade 0, 0603", Manufacturer=Vishay-Dale, Power_W=250mW, Supplier Part Number 1=541-2779-1-ND, Tolerance_%=0%, Value2=0.25W, Value_Code=0
R21: library part CMP-0022130-4, "RES, 1.65 k, 1%, 0.1 W, AEC-Q200 Grade 0, 0603", Manufacturer=Vishay-Dale, Power_W=100mW, Supplier Part Number 1=541-1.65KHCT-ND, TempCo="100 ppm/C", Tolerance_%=1%, Value2=0.1W, Value_Code=1k65, ValueDisplayed=1.65k
R23: library part CMP-0022601-2, "RES, 7.50 k, 1%, 0.1 W, 0603", Manufacturer=Vishay-Dale, Power_W=100mW, Supplier Part Number 1=541-7.50KHCT-ND, TempCo="100 ppm/C", Tolerance_%=1%, Value2=0.1W, Value_Code=7k50, ValueDisplayed=7.50k
R25: library part CMP-0022336-2, "RES, 332 k, 1%, 0.1 W, 0603", Manufacturer=Vishay-Dale, Power_W=100mW, Supplier Part Number 1=541-332KHCT-ND, TempCo="100 ppm/C", Tolerance_%=1%, Value2=0.1W, Value_Code=332k
R28: library part CMP-0022908-4, "RES, 20.0, 1%, 0.1 W, 0603", Manufacturer=Yageo, Power_W=100mW, Supplier Part Number 1=311-20.0HRCT-ND, TempCo="100 ppm/C", Tolerance_%=1%, Value2=0.1W, Value_Code=20R0, ValueDisplayed=20.0
R29: library part CMP-0022204-4, "RES, 20.0 k, 1%, 0.1 W, AEC-Q200 Grade 0, 0603", Manufacturer=Vishay-Dale, Power_W=100mW, Supplier Part Number 1=541-20.0KHCT-ND, TempCo="100 ppm/C", Tolerance_%=1%, Value2=0.1W, Value_Code=20k0, ValueDisplayed=20.0k
R31: library part CMP-0022235-5, "RES, 249, 1%, 0.1 W, AEC-Q200 Grade 0, 0603", Manufacturer=Vishay-Dale, Power_W=100mW, Supplier Part Number 1=541-249HCT-ND, TempCo="100 ppm/C", Tolerance_%=1%, Value2=0.1W, Value_Code=249R, ValueDisplayed=249
R32: library part CMP-0091402-1, "10 mOhms ±1% 3W Chip Resistor 2512 (6432 Metric) Anti-Sulfur, Automotive AEC-Q200, Current Sense, Moisture Resistant, Pulse Withstanding Metal Element", Digikey Part Number=541-10158-1-ND, Manufacturer=Vishay, Mouser Part Number=71-WSLP2512R0100FEA, Operating Temperature Range="-65°C to +170°C", Power_W=3W, TempCo=75ppm/°C, Tolerance_%=1%
R33: library part CMP-0022991-5, "RES, 2.40 k, 1%, 0.1 W, 0603", Manufacturer=Yageo, Power_W=100mW, Supplier Part Number 1=311-2.40KHRCT-ND, TempCo="100 ppm/C", Tolerance_%=1%, Value2=0.1W, Value_Code=2k40, ValueDisplayed=2.40k
S1: library part CMP-0081262-1, "Switch, Slide, 2 SPST, Off-On, 0.025 A, 24 VDC, SMT", CurrentRating_mA=25A, Manufacturer="Omron Electronic Components", Supplier Part Number 1=SW1190-ND
TP1 TP3 TP6: library part CMP-0055147-1, "Test Point, Multipurpose, Red, TH", Color=Red, Manufacturer=Keystone, Supplier Part Number 1=36-5010-ND
TP2 TP4 TP7: library part CMP-0055148-1, "Test Point, Multipurpose, Black, TH", Color=Black, Manufacturer=Keystone, Supplier Part Number 1=36-5011-ND
TP8: library part CMP-0055159-1, "Test Point, Multipurpose, Grey, TH", Color=Grey, Manufacturer=Keystone, Supplier Part Number 1=36-5128-ND
U1: library part CMP-0094198-1, "MOSFET DRVR 2A 2-OUT Hi/Lo Side Non-Inv 18-Pin LCC Space Level Screening", Manufacturer=Infineon, Max Power Dissipation=1.6W, Max Supply Voltage=20V, Min Supply Voltage=5V, Operating Temperature Range="-55°C to +125°C"
U2: library part CMP-0090357-2, "Radiation-Hardness-Assured Si and GaN Dual Output Controller", Manufacturer="Texas Instruments", Max Supply Voltage=14V, Min Supply Voltage=4V, Nominal Supply Current=10-15mA, Operating Temperature Range="-55°C to +125°C", Switching Frequency=200-4000kHz
U3: library part CMP-0081563-2, "Voltage Output, Unidirectional Measurement Current-Shunt Monitor, HKX0008A (CFP-8)", Alternate Manufacturer="Texas Instruments", Rating=Space
U4: library part CMP-0069991-1, "3-Terminal Adjustable Regulator, 3-pin TO-39", Manufacturer="Texas Instruments", PackageTopMarking="NSZXYTTE# LM117HP+", PartNumber=LM117H/NOPB, PowerWise=N

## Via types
v1: diameter 30, hole 12, Component Side to Solder Side, tented both sides, 112 vias
v2: diameter 30, hole 16, Component Side to Solder Side, tented both sides, 18 vias

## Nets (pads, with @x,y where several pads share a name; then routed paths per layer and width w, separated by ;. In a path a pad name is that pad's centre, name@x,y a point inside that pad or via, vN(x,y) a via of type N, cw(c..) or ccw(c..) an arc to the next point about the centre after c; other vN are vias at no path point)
COMP: C25.1 C29.1 U2.22 | length 152.3
  Component Side w10: U2.22@1933.56,1475.02 1933.56,1548.1 C29.1@1943.5,1558.04 1943.5,1622.54 C25.1@1943.99,1623.04
CS_ILIM: C39.1 R30.1 R31.2 U2.16 | length 231.6
  Component Side w10: U2.16@1933.56,1325.02 U2.16@1933.56,1326.23 ; U2.16@1933.56,1325.02 v1(1991.81,1325)
  Solder Side w10: v1(1991.81,1325) 1993.05,1323.76 R30.1@2162.59,1323.76 ; R30.1@2162,1326.1 R30.1@2162.59,1325.5
EN: C26.1 R8.1 R18.2 S1.1 U2.8 | length 749.9
  Component Side w10: S1.1@1349.4,893.04 1294.28,893.04 1280,907.32 1280,1100 1340.06,1160.06 R8.1@1340.06,1207.16 1340.06,1212.08 R18.2@1403.05,1275.07 1420.07,1275.07 1445.02,1300.02 U2.8@1528.44,1300.02 1585.98,1300.02 v1(1587,1299)
  Solder Side w10: v1(1587,1299) 1588.03,1300.03 C26.1@1647.78,1300.03
Fault: C200.1 R6.2 S1.2 U2.17 | length 887.5
  Component Side w10: S1.2@1349.4,993.04 1351.36,994.99 R6.2@1471,994.99 1481.01,1005 1489.01,997 v1@1525,997 ; v1(1526,997) 1577.88,997 C200.1@1579.88,999 ; v1(1875,1347) 1930.54,1347 U2.17@1933.56,1350.02
  Signal Layer 2 w10: v1@1525,997 1525,999 1660.48,999 1806,1144.52 1806,1303.22 1849.78,1347 v1(1875,1347)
